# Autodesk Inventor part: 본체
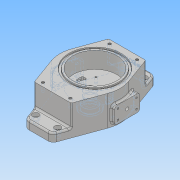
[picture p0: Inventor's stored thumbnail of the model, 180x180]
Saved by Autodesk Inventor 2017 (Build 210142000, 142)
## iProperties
Part Number: 본체
Material: 일반
Document SubType Name: Modeling
Designer: Administrator
Density: 1 g/cm^3
Appearance: 기본값
Mass: 579.925 g
Surface Area: 721.545 cm^2
Volume: 579.925 cm^3
Author: Administrator
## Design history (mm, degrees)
sketch "스케치1"
  geometry: L1 (-17.315, 94)-(17.315, 94); L2 (-17.315, -94)-(17.315, -94); L3 (-51.683, 18.811)-(-33.78, 68); L4 (26.711, 87.42)-(33.78, 68); L5 (-26.711, -87.42)-(-33.78, -68); L6 (26.711, -87.42)-(33.78, -68); L7 (0.846, 54.993)-(0.846, -54.993); L8 (-33.78, 68)-(33.78, 68); L9 (-33.78, -68)-(33.78, -68); L10 (-33.78, 68)-(-26.711, 87.42); L11 (33.78, 68)-(51.683, 18.811); L12 (33.78, -68)-(51.683, -18.811); L13 (-33.78, -68)-(-51.683, -18.811); A1 r 55 centre (0, 0) between (-51.683, -18.811) and (51.683, -18.811); A2 r 55 centre (0, 0) between (-51.683, 18.811) and (-51.683, -18.811); A3 r 55 centre (0, 0) between (51.683, 18.811) and (-51.683, 18.811); A4 r 55 centre (0, 0) between (51.683, -18.811) and (51.683, 18.811); A5 r 10 centre (-17.315, -84) between (-26.711, -87.42) and (-17.315, -94); A6 r 10 centre (17.315, -84) between (17.315, -94) and (26.711, -87.42); A7 r 10 centre (-17.315, 84) between (-17.315, 94) and (-26.711, 87.42); A8 r 10 centre (17.315, 84) between (26.711, 87.42) and (17.315, 94); 1 further point
  constraints: 34 tangent, 26 end point, 22 point on circle, 8 centre point, 4 horizontal, 3 equal radius, 1 coincident, 1 vertical
  dimensions: "d0" = 110 diameter of A1; "d1" = 188 distance between parallel lines of L2 L1; "d2" = 94 distance from line of L2 point (0, 0); "d3" = 20 deg angle of L7 L3; "d4" = 40 deg angle of L4 L3; "d5" = 20 deg angle of L5 L7; "d6" = 40 deg angle of L6 L5; "d7" = 10 radius of A5; "d11" = 136 distance between parallel lines of L9 L8; "d12" = 68 distance from line of L9 point (0, 0)
extrude "돌출1" new body sketch "스케치1" distance "d8" = 15; taper "d9" = 0 deg
extrude "돌출2" join sketch "스케치1" distance "d13" = 55; taper "d14" = 0 deg
sketch "스케치20"
  geometry: L1 (-9, 5)-(27, 5); L2 (32, 10)-(32, 30); L3 (27, 35)-(-9, 35); L4 (-14, 30)-(-14, 10); L5 (-14, 5)-(32, 35); L6 (32, 5)-(-14, 35); A1 r 5 centre (27, 30) between (32, 30) and (27, 35); A2 r 5 centre (27, 10) between (27, 5) and (32, 10); A3 r 5 centre (-9, 10) between (-14, 10) and (-9, 5); A4 r 5 centre (-9, 30) between (-9, 35) and (-14, 30); 2 further points
  constraints: 12 end point, 8 point on circle, 8 point on line, 8 tangent, 4 centre point, 3 equal radius, 2 midpoint, 2 parallel, 1 horizontal, 1 perpendicular
  dimensions: "d104" = 9 horizontal distance of point (9, 20) point (0, 0); "d105" = 20 vertical distance of point (9, 20) point (0, 0); "d106" = 46 distance of L5.end L6.end; "d107" = 30 distance of L6.start L5.end; "d110" = 5 radius of A1 (derived)
extrude "돌출11" join sketch "스케치20" stored distance "d108" = 118; taper "d109" = 0 deg
sketch "스케치3"
  geometry: C1 r 17.5 at (0, 0); A1 r 55 centre (0, 0) between (51.683, -18.811) and (51.683, 18.811) reference
  constraints: 1 centre point, 1 coincident
  dimensions: "d15" = 35 diameter of C1
extrude "돌출3" join sketch "스케치3" distance "d16" = 5; taper "d17" = 0 deg
sketch "스케치7"
  geometry: C1 r 40 at (0, 9); A1 r 55 centre (0, 0) between (-51.683, 18.811) and (-51.683, -18.811) reference
  constraints: 1 centre point, 1 vertical alignment
  dimensions: "d33" = 80 diameter of C1; "d34" = 9 distance of A1.centre C1.centre
extrude "돌출7" cut sketch "스케치7" distance "d35" = 30; taper "d36" = 0 deg
sketch "스케치8"
  geometry: C1 r 40 at (0, 9) reference; C2 r 47.5 at (0, 9); C3 r 43.4 at (0, 9)
  constraints: 2 centre point, 1 coincident
  dimensions: "d37" = 95 diameter of C2; "d38" = 4.1 radial gap between concentric circles of C2 C3
extrude "돌출8" cut sketch "스케치8" distance "d39" = 2.4; taper "d40" = 0 deg
sketch "스케치12"
  geometry: L1 (-40, 25)-(40, 25) reference; L2 (0, 0)-(0, 25); L3 (10, 25)-(10, 15); L4 (10, 15)-(8, 15); L5 (8, 15)-(8, 3.4); L6 (8, 3.4)-(12.3, 3.4); L7 (12.5, 3.2)-(12.5, -5); L8 (-17.5, -5)-(17.5, -5) reference; L9 (12.5, -5)-(0, -5); L10 (0, 0)-(0, -5); L11 (10, 25)-(0, 25); A1 r 0.2 centre (12.3, 3.2) between (12.5, 3.2) and (12.3, 3.4); 1 further point
  constraints: 18 end point, 5 perpendicular, 4 point on line, 2 midpoint, 2 point on circle, 2 tangent, 1 centre point, 1 horizontal, 1 vertical
  dimensions: "d51" = 20 diameter of L3 L2; "d52" = 10 distance of L3.start L3.end; "d53" = 16 diameter of L5 L2; "d54" = 25 diameter of L7 L10; "d55" = 8.4 distance of point (12.5, 3.4) L7.end; "d56" = 0.2 radius of A1
revolve "회전1" sketch "스케치12" stored, may be unused: angle "d57" = 90 deg
sketch "스케치15"
  geometry: A1 r 55 centre (0, 0) between (-51.683, 18.811) and (-51.683, -18.811) reference; 4 further points
  constraints: 2 horizontal alignment, 2 vertical alignment
  dimensions: "d73" = 50 distance of point (25, -61) point (-25, -61); "d74" = 25 horizontal distance of point (-25, -61) A1.centre; "d76" = 122 distance of point (-25, 61) point (-25, -61); "d77" = 61 vertical distance of A1.centre point (-25, -61)
hole "구멍4" sketch "스케치15" at (-25, -61), (25, -61), (-25, 61), (25, 61) diameter "d78" = 4.917; stored, may be unused: countersink angle "d82" = 90 deg, drill point angle "d84" = 118 deg; dims "d79" = 12, "d80" = 11, "d81" = 6.6, "d83" = 14
sketch "스케치17"
  geometry: L1 (26.702, 6)-(22.517, 6); L2 (-22.517, 6)-(-26.702, 6); L3 (26.702, -6)-(25.515, -6); L4 (-25.515, -6)-(-26.702, -6); C1 r 10 at (0, -9) reference; C2 r 40 at (0, 0) reference; A1 r 24 centre (0, -9) between (-20.785, 3) and (-23.552, -4.385); A2 r 29 centre (0, 0) between (-28.68, 4.296) and (-28.68, -4.296); A3 r 24 centre (0, -9) between (18.735, 6) and (-18.735, 6); A4 r 29 centre (0, 0) between (28.373, 6) and (-28.373, 6); A5 r 29 centre (0, 0) between (-28.373, -6) and (28.373, -6); A6 r 24 centre (0, -9) between (-23.812, -6) and (23.812, -6); A7 r 24 centre (0, -9) between (23.552, -4.385) and (20.785, 3); A8 r 29 centre (0, 0) between (28.68, -4.296) and (28.68, 4.296); A9 r 2 centre (-22.517, 4) between (-20.785, 3) and (-22.517, 6); A10 r 2 centre (-25.515, -4) between (-25.515, -6) and (-23.552, -4.385); A11 r 2 centre (-26.702, -4) between (-28.68, -4.296) and (-26.702, -6); A12 r 2 centre (-26.702, 4) between (-26.702, 6) and (-28.68, 4.296); A13 r 2 centre (22.517, 4) between (22.517, 6) and (20.785, 3); A14 r 2 centre (26.702, 4) between (28.68, 4.296) and (26.702, 6); A15 r 2 centre (25.515, -4) between (23.552, -4.385) and (25.515, -6); A16 r 2 centre (26.702, -4) between (26.702, -6) and (28.68, -4.296)
  constraints: 41 point on circle, 16 centre point, 16 tangent, 8 end point, 8 point on line, 7 equal radius, 4 horizontal, 2 coincident, 1 collinear
  dimensions: "d89" = 12 distance between parallel lines of L3 L1; "d90" = 12 distance between parallel lines of L4 L2; "d91" = 6 distance from line of L4 C2.centre; "d92" = 48 diameter of A1; "d93" = 58 diameter of A2; "d94" = 2 radius of A9 (derived)
extrude "돌출10" cut sketch "스케치17" distance "d95" = 12; taper "d96" = 0 deg
fillet "모깎기1" dims "d97" = 2
sketch "스케치22"
  geometry: L1 (0, 18.811)-(0, -18.811) reference; 2 further points
  dimensions: "d113" = 9 vertical distance of point (0, 0) point (-20, 9); "d114" = 20 distance from line of point (-20, 9) L1
hole "구멍5" sketch "스케치22" at (-20, 9) diameter "d115" = 6; stored, may be unused: countersink angle "d119" = 90 deg, drill point angle "d121" = 118 deg; dims "d116" = 12, "d117" = 11, "d118" = 6.6, "d120" = 14
sketch "스케치23"
  geometry: C1 r 3 at (-20, 9) reference; 5 further points
  constraints: 2 horizontal alignment, 2 vertical alignment
  dimensions: "d122" = 17 vertical distance of point (-29, 26) C1.centre; "d123" = 34 distance of point (-29, 26) point (-29, -8); "d124" = 9 horizontal distance of point (-29, 26) C1.centre; "d125" = 18 distance of point (-11, 26) point (-29, 26)
hole "구멍6" sketch "스케치23" at (-29, 26), (-11, 26), (-11, -8), (-29, -8) diameter "d126" = 3.242; stored, may be unused: countersink angle "d130" = 90 deg, drill point angle "d132" = 118 deg; dims "d127" = 8, "d128" = 11, "d129" = 6.6, "d131" = 10
sketch "스케치24"
  geometry: A1 r 24 centre (0, -9) between (-20.785, 3) and (-23.552, -4.385) reference; 2 further points
  constraints: 1 horizontal alignment
  dimensions: "d133" = 26 vertical distance of point (15, 17) A1.centre; "d134" = 30 distance of point (15, 17) point (-15, 17); "d135" = 15 horizontal distance of A1.centre point (15, 17)
hole "구멍7" sketch "스케치24" at (-15, 17), (15, 17) diameter "d136" = 3.242; stored, may be unused: countersink angle "d140" = 90 deg, drill point angle "d142" = 118 deg; dims "d137" = 8, "d138" = 11, "d139" = 6.6, "d141" = 10
sketch "스케치25"
  geometry: L1 (67.56, -40)-(0, -40) reference; L2 (8.892, -21.398)-(58.667, -21.398); L3 (58.667, -21.398)-(58.667, -28.602); L4 (58.667, -28.602)-(8.892, -28.602); L5 (8.892, -28.602)-(8.892, -21.398); L6 (51.094, 15)-(16.465, 15) reference; L7 (58.667, -25)-(8.892, -25); 3 further points
  constraints: 4 midpoint, 2 end point, 1 vertical alignment, 2 other
  dimensions: "d143" = 15 distance between parallel lines of L1 L7
feature "엠보싱1" sketch "스케치25" dims "d0" = 110, "d1" = 188, "d2" = 94, "d3" = 20 deg, "d4" = 40 deg, "d5" = 20 deg, "d6" = 40 deg, "d7" = 10, "d11" = 136, "d12" = 68, "d144" = 0.5, "d145" = 0
chamfer "모따기1" distance "d146" = 1; stored, may be unused: second distance "d147" = 2, angle "d148" = 30 deg
fillet "모깎기4" dims "d154" = 3
fillet "모깎기5" dims "d155" = 3
chamfer "모따기3" distance "d156" = 0.4; stored, may be unused: second distance "d157" = 2, angle "d158" = 30 deg
fillet "모깎기6" dims "d159" = 0.5
sketch "스케치26"
  geometry: 5 further points
  constraints: 2 horizontal alignment
  dimensions: "d160" = 79 vertical distance of point (20, -79) point (0, 0); "d161" = 40 distance of point (20, -79) point (-20, -79); "d162" = 20 horizontal distance of point (0, 0) point (20, -79); "d163" = 40 distance of point (20, 79) point (-20, 79); "d164" = 20 horizontal distance of point (0, 0) point (20, 79); "d165" = 158 distance of point (20, 79) point (20, -79)
hole "구멍8" sketch "스케치26" at (-20, -79), (20, -79), (-20, 79), (20, 79) diameter "d166" = 6.6; stored, may be unused: countersink angle "d170" = 90 deg, drill point angle "d172" = 118 deg; dims "d167" = 8, "d168" = 11, "d169" = 6.6, "d171" = 10
node "솔리드1"
mirror "미러1"
other parameters: "d85" = 48, "d86" = 58, "d87" = 6, "d88" = 12
